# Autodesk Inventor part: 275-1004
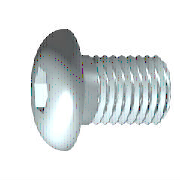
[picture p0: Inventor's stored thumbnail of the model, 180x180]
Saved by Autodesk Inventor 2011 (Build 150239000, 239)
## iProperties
IsCustomPart: 0
Company: Autodesk Inc.
Created: 2010-02
Part Number: 275-1004
Material: Steel, Mild
Description: Hexagon Socket Button Head Cap Screw
Document SubType Name: Modeling
Standard: ANSI B18.3
Designer: Autodesk Inc.
Standard Revision: 2003
Standards Organization: ANSI
Language: en-US
Size Designation: 8 - 32 x 1/2
Categories: <MemberInstance><Categories><Category DisplayName="Fasteners" InternalName="e4da775c-781d-43d5-af7c-5136215cf5a6" Mnemonic="FSTN"><Category DisplayName="Bolts"
Density: 1 g/cm^3
Catalog Web Link: http://www.vexrobotics.com/screws-8-32.html
Vendor: Innovation First, Inc.
Author: Autodesk Inc.
Title: VEX Robotics Kit of Parts
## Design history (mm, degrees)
workplane "Work Plane1"
fillet "Fillet2" dims "d30" = 0.1 (= R)
revolve "Body" stored, may be unused: angle "d10" = 90 deg
sketch "Sketch2"
  geometry: L1 (0, -5.547)-(0, 5.547) reference; L2 (-5.547, 0)-(5.547, 0) reference; L3 (1.378, 0)-(0.689, -1.194); L4 (0.689, -1.194)-(-0.689, -1.194); L5 (-0.689, -1.194)-(-1.378, 0); L6 (-1.378, 0)-(-0.689, 1.194); L7 (-0.689, 1.194)-(0.689, 1.194); L8 (0.689, 1.194)-(1.378, 0); 2 further points
  constraints: 12 end point, 1 coincident, 1 horizontal alignment, 1 point on line, 12 other
extrude "Slot" join sketch "Sketch2" stored distance "d11" = 10; taper "d12" = 0 deg
body "Solid1"
fillet "Fillet1" dims "d17" = 1.9558 (= RR)
feature "Thread" dims "d13" = 11.10976 (= GEL), "d14" = 0
chamfer "Chamfer1" distance "d15" = 0.48692 (= -0.5 x SPD + 0.5 x GD); stored, may be unused: second distance "d16" = 0.48692 (= GUL), angle "d27" = 45 deg
sketch "Sketch1"
  geometry: L1 (-0.093, 0)-(12.7, 0); L2 (12.7, 0)-(12.7, 2.083); L3 (12.7, 2.083)-(1.59, 2.083); L4 (1.59, 2.083)-(0, 2.083); L5 (0, 2.083)-(0, 2.083); L6 (0, 2.083)-(0, 3.962); L7 (0, 3.962)-(-2.21, 3.962); L8 (-2.21, 3.962)-(-2.21, 1.378); L9 (-2.21, 1.378)-(-0.889, 1.378); L10 (-0.889, 1.378)-(-0.093, 0); L11 (-5.192, 0)-(15.682, 0) reference; L12 (0, -0.792)-(0, 4.755) reference; L13 (1.59, 2.083)-(0, 2.083)
  constraints: 22 end point, 6 parallel, 2 collinear, 2 perpendicular, 1 horizontal, 1 point on line
  dimensions: "d1" = 11.10976 distance from line of L3.end L2 (= GEL); "d2" = 1.59014 distance of L4.end L3.end (computed from GAL); "d3" = 2.2098 distance between parallel lines of L8 L6 (= KOH); "d4" = 1.3208 distance of L8.end L9.end (= INTI); "d5" = 60 deg angle of L10 L1; "d6" = 4.1656 diameter of L3 L1 (= GD); "d7" = 4.1656 diameter of L5 L1 (= BDM); "d8" = 2.75696 diameter of L9 L1 (= 1.1547 x SW); "d9" = 7.9248 diameter of L7 L1 (= KOD); "d26" = 12.7 distance between parallel lines of L12 L2 (= NLG)
other parameters: "GD" = 4.1656 (= NND) [user parameter; used in 2 equation terms], "NLG" = 12.7 [user parameter; used in 1 equation term], "GEL" = 11.10976 [user parameter; used in 2 equation terms], "KOD" = 7.9248 [user parameter; used in 1 equation term], "KOH" = 2.2098 [user parameter; used in 1 equation term], "INTI" = 1.3208 [user parameter; used in 1 equation term], "GAL" = 1.59004 [user parameter; used in 1 equation term], "GUL" = 0.48692 [user parameter; used in 1 equation term], "BDM" = 4.1656 (= NND) [user parameter; used in 1 equation term], "SW" = 2.3876 [user parameter; used in 1 equation term], "RR" = 1.9558 [user parameter; used in 1 equation term], "SPD" = 3.19176 [user parameter; used in 2 equation terms], "d19" = 0, "d28" = 0, "d29" = 0, "R" = 0.1 [user parameter; used in 1 equation term], "TOA" = 30 deg [user parameter], "GD1" = 3.19176 (= SPD) [user parameter], "THREADDIA" = 4.1656 [user parameter], "PTC" = 0.79375 (computed from TPU) [user parameter], "KOH1" = 0.381 [user parameter], "NND" = 4.1656 [user parameter; used in 2 equation terms], "E0" = 2.75768 [user parameter]
